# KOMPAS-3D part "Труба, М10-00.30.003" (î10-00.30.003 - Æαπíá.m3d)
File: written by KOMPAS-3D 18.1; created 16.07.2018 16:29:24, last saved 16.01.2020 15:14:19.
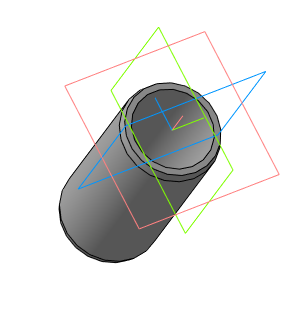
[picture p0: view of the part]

Document properties: Автор: Милов; Полное имя файла: D:\Magna\Магна Ins\Магна ins 10\М10-00.00.000\3Д\М10-00.30.003 - Труба.m3d

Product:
- Part/product: Труба  | designation М10-00.30.003
    Масса: 0.021849
    Раздел спецификации: Детали
    Форматы листов документа: A4
    source file: М10-00.30.003 - Труба.cdw
  - Component [billet]: Труба 32 PN10 S=2,9 FV PPR ф. "FV PLAST"  | Материал: Труба 32 PN10 S=2,9 FV PPR ф. "FV PLAST" (density 0 kg/m3); Раздел спецификации: Материалы; Примечание: м; source file: Труба 32 PN10 S=2,9 FV PPR ф. FV PLAST.m3d
- Part/product: Труба  | designation М13-01.30.003
    Масса: 0.0162255
    Раздел спецификации: Детали
    Форматы листов документа: A4
    source file: ..\..\..\Магна ins 13\М13-01.00.000 ПВХ\Чертежи Компас\М13-01.30.003 - Труба.cdw
  - Component [billet]: Труба 32 PN16 ПВХ  | designation 01  | Материал: Труба 32 PN10 НПВХ (density 0 kg/m3); Раздел спецификации: Материалы; Примечание: м

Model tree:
1. Эскиз:1  (with: Операция выдавливания:1)
2. Вырезать элемент выдавливания:1  (labels: Труба 32 PN10 S=2,9 FV PPR ф. "FV PLAST")
     Расстояние 1 = 50
3. Эскиз:3  (with: Вырезать элемент выдавливания:5, Вырезать элемент выдавливания:6)
4. Элемент выдавливания:1
     Расстояние 2 = 57
5. Элемент выдавливания:2  (with: Элемент выдавливания:1, Элемент выдавливания:6)
     Расстояние 1 = 2.00022
6. Элемент выдавливания:3  (with: Элемент выдавливания:2, Вырезать элемент выдавливания:8)  (labels: Колено 90@1~ @2~40FV PPR ф. "FV PLAST")
     Расстояние 1 = 0.9
7. Фаска:3  (with: Элемент выдавливания:2)  (labels: Труба 32 PN10 НПВХ)
     Угол = 15; Длина 1 = 3; Длина 2 = 0.803848

Referenced files in D:\Magna\Магна Ins\Магна ins 10\М10-00.00.000\3Д\: Труба 32 PN10 S=2,9 FV PPR ф. FV PLAST.m3d, М10-00.20.000 - Корпус.a3d, М10-00.30.000 - Обечайка.a3d
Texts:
  Body Specification ( left align )
  Body Specificaton ( centered )
  Полипропилен  ГОСТ 26996-86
